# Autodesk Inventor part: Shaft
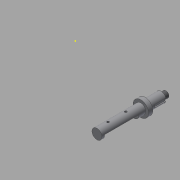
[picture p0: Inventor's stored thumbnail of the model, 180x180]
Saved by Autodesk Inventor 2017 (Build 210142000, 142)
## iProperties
Created: 2009-04
Part Number: Shaft
Document SubType Name: Modeling
Designer: Sham
Density: 1 g/cm^3
Material: Generic
Appearance: Default
Author: Sham
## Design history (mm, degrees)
sketch "Sketch1"
  geometry: C1 r 18 at (511.175, 103.188)
  constraints: 1 centre point
  dimensions: "d0" = 36 diameter of C1
extrude "Extrusion1" new body sketch "Sketch1" distance "d1" = 28.9; taper "d2" = 0 deg
sketch "Sketch2"
  geometry: C1 r 28 at (0, 0)
  constraints: 1 centre point
  dimensions: "d3" = 56 diameter of C1
extrude "Extrusion2" join sketch "Sketch2" distance "d4" = 89.8; taper "d5" = 0 deg
sketch "Sketch3"
  geometry: C1 r 43.6 at (0, 0)
  constraints: 1 centre point
  dimensions: "d6" = 87.2 diameter of C1
extrude "Extrusion3" join sketch "Sketch3" distance "d7" = 24; taper "d8" = 0 deg
sketch "Sketch4"
  geometry: C1 r 43.6 at (0, 0) reference; C2 r 28 at (0, 0)
  constraints: 1 centre point, 1 coincident
  dimensions: "d9" = 56 diameter of C2
extrude "Extrusion4" join sketch "Sketch4" distance "d10" = 247.1; taper "d11" = 0 deg
workplane "Work Plane1"
sketch "Sketch5"
  geometry: L1 (-27.828, 3.1)-(27.828, 3.1); C1 r 43.6 at (0, 0) reference; C2 r 28 at (0, 0) reference; A1 r 28 centre (0, 0) between (-27.828, 3.1) and (27.828, 3.1)
  constraints: 3 point on circle, 2 end point, 1 centre point, 1 concentric, 1 horizontal, 1 point on line
  dimensions: "d13" = 56 diameter of A1; "d51" = 3.1 vertical distance of A1.centre L1.start
extrude "Extrusion5" cut sketch "Sketch5" distance "d14" = 193.8; taper "d15" = 0 deg
sketch "Sketch6"
  geometry: L1 (-26.833, -8)-(-22, -8); L2 (-22, -8)-(-22, 8); L3 (-22, 8)-(-26.833, 8); L4 (-2.576, 0)-(-54.939, 0); L5 (-28, 0)-(7.224, 0); L6 (-10.388, -15.035)-(-10.388, 12.487); C1 r 18 at (0, 0) reference; A1 r 28 centre (0, 0) between (-26.833, 8) and (-26.833, -8); 3 further points
  constraints: 12 end point, 3 point on circle, 2 coincident, 2 horizontal, 1 centre point, 1 collinear, 1 parallel, 1 perpendicular, 1 point on line, 1 vertical, 1 other
  dimensions: "d28" = 16 distance of L3.end L1.start; "d31" = 28 radius of A1; "d32" = 6 distance from line of L5.start L2
extrude "Extrusion6" cut sketch "Sketch6" distance "d33" = 62.5; taper "d34" = 0 deg
chamfer "Chamfer1" distance "d35" = 3; stored, may be unused: second distance "d36" = 2, angle "d37" = 45 deg
sketch "Sketch7"
  geometry: 1 further point
hole "Hole2" diameter "d41" = 12.5; stored, may be unused: countersink angle "d45" = 90 deg, drill point angle "d47" = 118 deg; dims "d39" = 28, "d40" = 46.9, "d42" = 6, "d43" = 4, "d44" = 2, "d46" = 8
pattern_linear "Rectangular Pattern2" dims "d50" = 100
thread "Thread1" dims "d52" = 10, "d53" = 0
body "Solid1"
other parameters: "d12" = -15.1
